// Mitsubishi GX Works2 project: 44   PLC: FX1S

PROGRAM MAIN
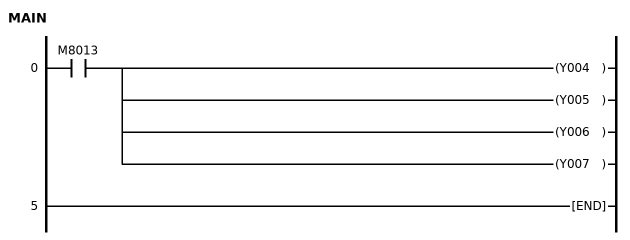
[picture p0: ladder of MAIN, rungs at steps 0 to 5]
0     LD      M8013
      OUT     Y004
      OUT     Y005
      OUT     Y006
      OUT     Y007
5     END
END_PROGRAM
